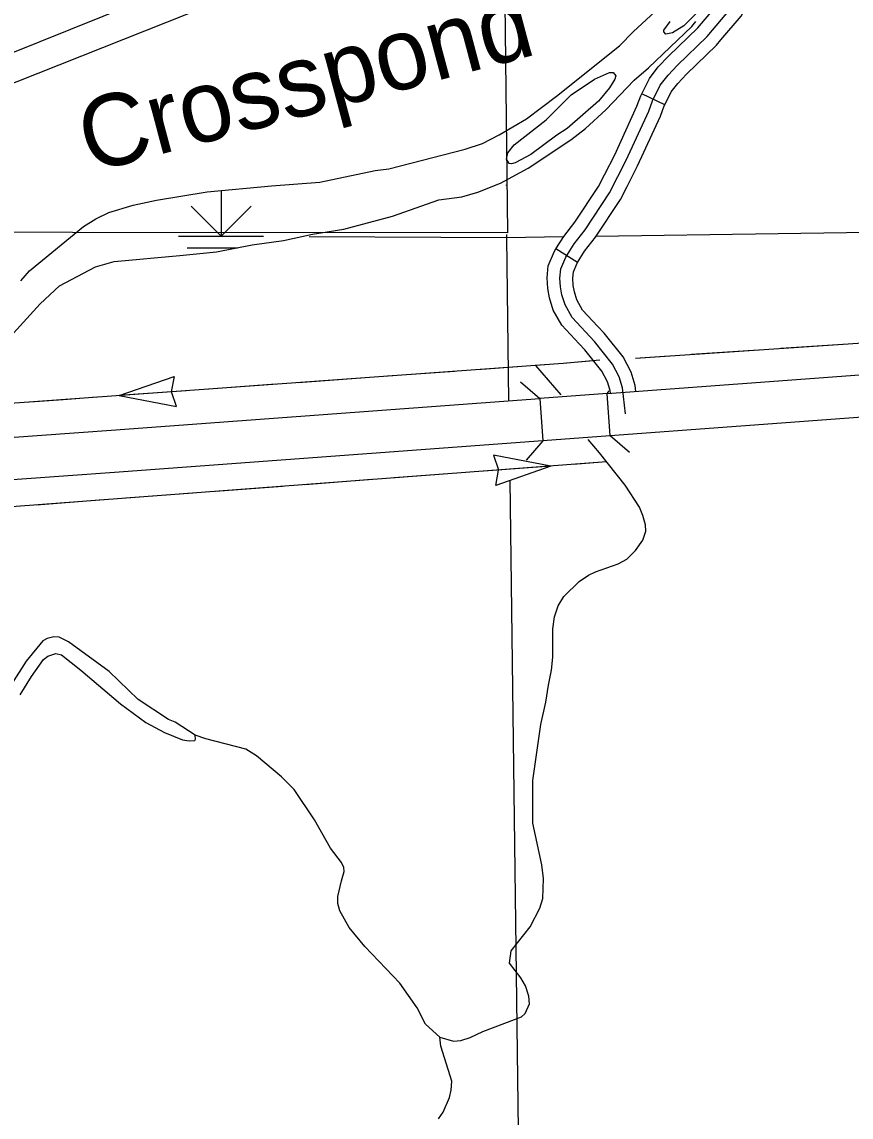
# Model space of a CAD drawing. Extents: x 1084508 to 1142749, y 1057638 to 1093403.
# Drawn here: x 1088600 to 1090132, y 1067055 to 1069080 of the extents above; entities that cross this region are included whole.
import ezdxf

# ---------------------------------------------------------------- set-up
doc = ezdxf.new("R2010")
doc.units = 0
for name, color, linetype in [('Level 15', 7, 'Continuous'), ('Level 35', 7, 'Continuous'), ('Level 37', 7, 'Continuous'), ('Level 43', 7, 'Continuous'), ('Level 44', 7, 'Continuous'), ('Level 45', 7, 'Continuous'), ('Level 47', 7, 'Continuous'), ('Level 5', 7, 'Continuous'), ('Level 7', 7, 'Continuous')]:
    doc.layers.add(name, color=color, linetype=linetype)

msp = doc.modelspace()

# ---------------------------------------------------------------- linework, layer by layer
at = {"layer": 'Level 15'}
for p, q in [((1089557.4, 1068383.6), (1089563.1, 1068305.3)), ((1089687.4, 1068314.5), (1089681.7, 1068392.8))]:
    msp.add_line(p, q, dxfattribs=at)
for points in [[(1089681.7, 1068392.8), (1090405.7, 1068446.3), (1090992.2, 1068488.9)], [(1090998.2, 1068410.7), (1090411.4, 1068368.1), (1089687.4, 1068314.5)], [(1088508.3, 1068306.4), (1088765.3, 1068325), (1089557.4, 1068383.6)], [(1089681.7, 1068392.8), (1089557.4, 1068383.6)], [(1089563.1, 1068305.3), (1088771.1, 1068246.7), (1088514, 1068228.2)], [(1089687.4, 1068314.5), (1089563.1, 1068305.3)]]:
    msp.add_lwpolyline(points, dxfattribs=at)
at = {"layer": 'Level 35'}
for points in [[(1089854.8, 1069103.8), (1089823.3, 1069072), (1089802.4, 1069059.3), (1089790.2, 1069057.1), (1089786.3, 1069061.3), (1089786.2, 1069064.5), (1089798.3, 1069080)], [(1089569.2, 1068898.5), (1089615.4, 1068944.7), (1089658.3, 1068973.8), (1089685.8, 1068986), (1089693, 1068985.9), (1089697.9, 1068980.1), (1089695.9, 1068973.7), (1089686.1, 1068957.4), (1089665.9, 1068933.1), (1089607.7, 1068882.8), (1089588.6, 1068870.2)], [(1089588.6, 1068870.2), (1089540.6, 1068834.7), (1089511.6, 1068819), (1089505.1, 1068817.2), (1089500.4, 1068817.7), (1089495.4, 1068826), (1089497.9, 1068837.4), (1089509.9, 1068852.2), (1089569.2, 1068898.5)], [(1089596.6, 1068390.2), (1089549.6, 1068444.5)], [(1089372.4, 1067203), (1089397.7, 1067195.6), (1089411.4, 1067197), (1089428.8, 1067202.6), (1089452.2, 1067213.5), (1089492.8, 1067228.9), (1089523.1, 1067240.9), (1089530.1, 1067247.1), (1089538.3, 1067264.7), (1089537, 1067278.8), (1089531, 1067298.1), (1089522.4, 1067312.6), (1089501.5, 1067339.6), (1089504.2, 1067362.6), (1089539.4, 1067407.2), (1089557.1, 1067441.7), (1089562.5, 1067459.2), (1089564.1, 1067496.3), (1089560.8, 1067521.7), (1089544.2, 1067598.8), (1089544.5, 1067677.7), (1089559.1, 1067781), (1089568.4, 1067822.5), (1089573, 1067853.8), (1089579, 1067881.7), (1089581.4, 1067905.3), (1089581, 1067957.5), (1089584.6, 1067980), (1089591.2, 1068000), (1089601.9, 1068017.6), (1089629.9, 1068045), (1089647, 1068056.8), (1089660.3, 1068063.2), (1089702.1, 1068078.1), (1089718.1, 1068086.8), (1089734.3, 1068102.5), (1089747.4, 1068121.7), (1089752.9, 1068138), (1089752.3, 1068149.8), (1089747.5, 1068167.5), (1089741.3, 1068182.5), (1089714.7, 1068223.5), (1089667.6, 1068283), (1089646.7, 1068307.8)], [(1088920.7, 1067761.4), (1088883.3, 1067785), (1088870.9, 1067790.2), (1088814.9, 1067827.1), (1088761.8, 1067878.8), (1088686.7, 1067933.9), (1088669.2, 1067942.4), (1088659.2, 1067943.3), (1088647.1, 1067940.1), (1088638.7, 1067935.4), (1088608.3, 1067898), (1088580.8, 1067855.3), (1088557.2, 1067812), (1088544, 1067792.4), (1088533.7, 1067781.7), (1088525.1, 1067776.7), (1088512.9, 1067775.4), (1088507.5, 1067777.7), (1088500.3, 1067785.6), (1088483.5, 1067841.1), (1088478.7, 1067865.1)], [(1088597.1, 1067835.7), (1088618.3, 1067869.4), (1088640.5, 1067901.2), (1088648.1, 1067907.1), (1088662.7, 1067912.3), (1088673.7, 1067909.9), (1088709.4, 1067881.2), (1088782.5, 1067819.4), (1088829.1, 1067784.5), (1088863.5, 1067766.1), (1088896.9, 1067752.7), (1088909.5, 1067750.9), (1088919.8, 1067751.3), (1088921.3, 1067753.8), (1088920.7, 1067761.4)], [(1089370.3, 1067052), (1089378.4, 1067064.2), (1089390.3, 1067091.6), (1089393.7, 1067105.3), (1089394.4, 1067121.9), (1089374.1, 1067186.7), (1089372.4, 1067203), (1089346.2, 1067227), (1089330.5, 1067257.3), (1089298.6, 1067303.1), (1089234.1, 1067370.7), (1089204.8, 1067405.6), (1089187.8, 1067436.8), (1089183.9, 1067449.9), (1089184.1, 1067463.1), (1089191, 1067492), (1089195.8, 1067509.1), (1089194.9, 1067516.6), (1089190.9, 1067525.9), (1089170.3, 1067552.3), (1089141, 1067604.5), (1089103.2, 1067660.8), (1089079.9, 1067684.2), (1089033.8, 1067723.3), (1089014, 1067735.2), (1088940.4, 1067754.5), (1088920.7, 1067761.4)]]:
    msp.add_lwpolyline(points, dxfattribs=at)
at = {"layer": 'Level 37'}
for points in [[(1089521.8, 1068414.4), (1089557.4, 1068383.6)], [(1089681.6, 1068392.8), (1089685.6, 1068397.4)], [(1089563.1, 1068305.3), (1089532.3, 1068269.7)], [(1089723.1, 1068283.8), (1089687.4, 1068314.5)]]:
    msp.add_lwpolyline(points, dxfattribs=at)
at = {"layer": 'Level 43'}
for p, q in [((1088780.1, 1068388.8), (1088881.8, 1068424.1)), ((1088881.8, 1068424.1), (1088876.4, 1068396)), ((1088780.1, 1068388.8), (1088885.9, 1068368.5)), ((1088885.9, 1068368.5), (1088876.5, 1068395.6)), ((1089577.4, 1068258.6), (1089471.5, 1068278.5)), ((1089471.5, 1068278.5), (1089481, 1068251.5)), ((1089577.4, 1068258.6), (1089475.7, 1068222.9)), ((1089475.7, 1068222.9), (1089481.1, 1068251.1))]:
    msp.add_line(p, q, dxfattribs=at)
for points in [[(1089734.1, 1068458.3), (1091012.5, 1068544.5), (1091205.3, 1068556.8), (1092034, 1068615.4)], [(1090002.8, 1068476.4), (1090126.8, 1068484.8)], [(1089837.4, 1068465.2), (1089961.4, 1068473.6)], [(1089668.4, 1068454.5), (1089600.3, 1068448.2), (1088501.7, 1068368.7)], [(1089565.2, 1068445.6), (1089441.3, 1068436.7)], [(1089656.4, 1068453.4), (1089606.6, 1068448.8)], [(1089734.1, 1068458.3), (1089796.1, 1068462.4)], [(1089399.9, 1068433.7), (1089276, 1068424.7)], [(1089069.3, 1068409.8), (1088945.4, 1068400.8)], [(1089234.6, 1068421.7), (1089110.7, 1068412.7)], [(1088738.8, 1068385.8), (1088676.8, 1068381.3)], [(1088904, 1068397.8), (1088780.1, 1068388.8)], [(1088676.8, 1068381.3), (1088614.8, 1068376.8)], [(1089680.7, 1068266.4), (1088442.6, 1068172.6)], [(1089680.7, 1068266.4), (1089618.7, 1068261.7)], [(1089412.1, 1068246.1), (1089288.2, 1068236.7)], [(1089577.4, 1068258.6), (1089453.5, 1068249.2)], [(1089081.6, 1068221), (1088957.7, 1068211.6)], [(1089246.9, 1068233.6), (1089122.9, 1068224.2)], [(1088916.4, 1068208.5), (1088792.4, 1068199.1)], [(1088689.1, 1068191.3), (1088627.2, 1068186.6)], [(1088751.1, 1068196), (1088689.1, 1068191.3)]]:
    msp.add_lwpolyline(points, dxfattribs=at)
at = {"layer": 'Level 44'}
for p, q in [((1088968.4, 1068768.1), (1088968.4, 1068683.6)), ((1088968.4, 1068683.6), (1088912.9, 1068739.1)), ((1088968.4, 1068683.6), (1089023.9, 1068739.1)), ((1088889.9, 1068683.6), (1089046.9, 1068683.6)), ((1088905.6, 1068662.2), (1088998.5, 1068662.2))]:
    msp.add_line(p, q, dxfattribs=at)
at = {"layer": 'Level 45'}
for p, q in [((1089788, 1068926), (1089745.7, 1068946.8)), ((1089626.9, 1068635), (1089587, 1068660))]:
    msp.add_line(p, q, dxfattribs=at)
for points in [[(1089855.9, 1069076.3), (1089890.4, 1069117.5), (1089901.3, 1069136.1), (1089932.6, 1069209.7), (1089933.2, 1069211.4)], [(1089891.9, 1069046.1), (1089929.1, 1069090.3), (1089943.5, 1069114.9), (1089976.6, 1069192.8), (1089977.7, 1069196.1)], [(1089715.6, 1068355.3), (1089710.2, 1068403), (1089704.1, 1068423.5), (1089691.6, 1068447.2), (1089658.3, 1068488.7), (1089617.1, 1068533), (1089604, 1068556.4), (1089598.2, 1068575), (1089595.5, 1068589.7), (1089594.5, 1068606), (1089596.1, 1068623), (1089605.2, 1068644.8), (1089620.6, 1068669.3), (1089640.9, 1068695.5), (1089686.2, 1068763.4), (1089716.8, 1068823.7), (1089758.4, 1068914.6), (1089765.5, 1068933.8), (1089779.8, 1068962.6), (1089794.1, 1068981.1), (1089811.6, 1068999.7), (1089866.6, 1069052.5), (1089909.8, 1069103.9)], [(1089745.7, 1068946.8), (1089759.7, 1068975.2), (1089776.2, 1068996.4), (1089794.8, 1069016.3), (1089849.4, 1069068.6), (1089855.9, 1069076.3)], [(1089788, 1068926), (1089799.9, 1068950.1), (1089812, 1068965.8), (1089828.3, 1068983.2), (1089883.8, 1069036.4), (1089891.9, 1069046.1)], [(1089676.7, 1068796.6), (1089695.6, 1068833.9), (1089736.7, 1068923.6), (1089743.9, 1068943.1), (1089745.7, 1068946.8)], [(1089718.7, 1068775.3), (1089738, 1068813.5), (1089780.2, 1068905.6), (1089787.2, 1068924.4), (1089788, 1068926)], [(1089587, 1068660), (1089601.3, 1068682.8), (1089621.8, 1068709.3), (1089665.9, 1068775.3), (1089676.7, 1068796.6)], [(1089626.9, 1068635), (1089639.9, 1068655.8), (1089660, 1068681.8), (1089706.6, 1068751.5), (1089718.7, 1068775.3)], [(1089629.9, 1068484.6), (1089597.9, 1068519), (1089582.2, 1068547), (1089575.3, 1068569.3), (1089572, 1068586.8), (1089570.9, 1068606.4), (1089572.9, 1068628.8), (1089584.3, 1068655.7), (1089587, 1068660)], [(1089664.4, 1068516.7), (1089636.2, 1068546.9), (1089625.7, 1068565.7), (1089621.1, 1068580.7), (1089618.9, 1068592.5), (1089618.1, 1068605.6), (1089619.2, 1068617.3), (1089626.2, 1068633.9), (1089626.9, 1068635)], [(1089734.6, 1068396.7), (1089733.3, 1068407.7), (1089726, 1068432.4), (1089711.3, 1068460.2), (1089676.1, 1068504.1), (1089664.4, 1068516.7)], [(1089687.6, 1068393.2), (1089687, 1068398.2), (1089682.2, 1068414.6), (1089671.8, 1068434.2), (1089640.5, 1068473.3), (1089629.9, 1068484.6)]]:
    msp.add_lwpolyline(points, dxfattribs=at)
at = {"layer": 'Level 47'}
for points in [[(1088598.3, 1068600.7), (1088614.6, 1068619.5), (1088714.4, 1068701.4), (1088737.2, 1068715.3), (1088760.9, 1068727.1), (1088805.6, 1068740.8), (1088849.2, 1068749.8), (1088942.7, 1068765.7), (1089061.2, 1068776.8), (1089150.8, 1068783.2), (1089253.2, 1068804.8), (1089278.5, 1068807.9), (1089419, 1068844.5), (1089451.2, 1068855), (1089482.4, 1068870.5), (1089532.5, 1068900.5), (1089587.9, 1068942.5), (1089704.6, 1069035), (1089730.4, 1069062), (1089793.4, 1069119.4)], [(1088578.7, 1068497.2), (1088633.8, 1068558.2), (1088669.7, 1068592), (1088736.3, 1068626.6), (1088771, 1068636.5), (1088891.8, 1068647.7), (1088959.7, 1068654.7), (1089025.8, 1068667.5), (1089083.8, 1068675.7), (1089137.3, 1068687.2), (1089195.3, 1068696.7), (1089284.8, 1068720.4), (1089370.6, 1068750.5), (1089413, 1068756.3), (1089442.9, 1068764.8), (1089484.3, 1068781.3), (1089535.4, 1068809.1), (1089614.6, 1068861.3), (1089641.5, 1068882.3), (1089678.9, 1068917.2), (1089731.7, 1068971.8), (1089758.2, 1068994.9), (1089837.9, 1069070.8), (1089845.7, 1069080.1)]]:
    msp.add_lwpolyline(points, dxfattribs=at)
at = {"layer": 'Level 5'}
for points in [[(1089494.8, 1068778.1), (1089494.9, 1068777.4)], [(1089495.6, 1068686.4), (1089495.7, 1068680.7), (1089499.6, 1068379.3)], [(1090430.5, 1068697.4), (1090334.2, 1068692.8), (1089660.9, 1068683.1)], [(1089600.9, 1068682.2), (1089495.7, 1068680.7), (1089131.2, 1068682.1)], [(1089501.6, 1068232), (1089517.2, 1067031)]]:
    msp.add_lwpolyline(points, dxfattribs=at)
at = {"layer": 'Level 7'}
msp.add_lwpolyline([(1089929, 1069564.2), (1087629.5, 1068639.4)], dxfattribs=at)
msp.add_lwpolyline([(1089490.2, 1069326.9), (1089497.8, 1068689.6), (1087889.6, 1068691.1)], close=True, dxfattribs=at)

# ---------------------------------------------------------------- texts
at = {"layer": 'Level 35'}
msp.add_text('Crosspond', height=132.58, rotation=14.9043, dxfattribs=at).set_placement((1088725.8, 1068799.8))

doc.saveas('drawing.dxf')
